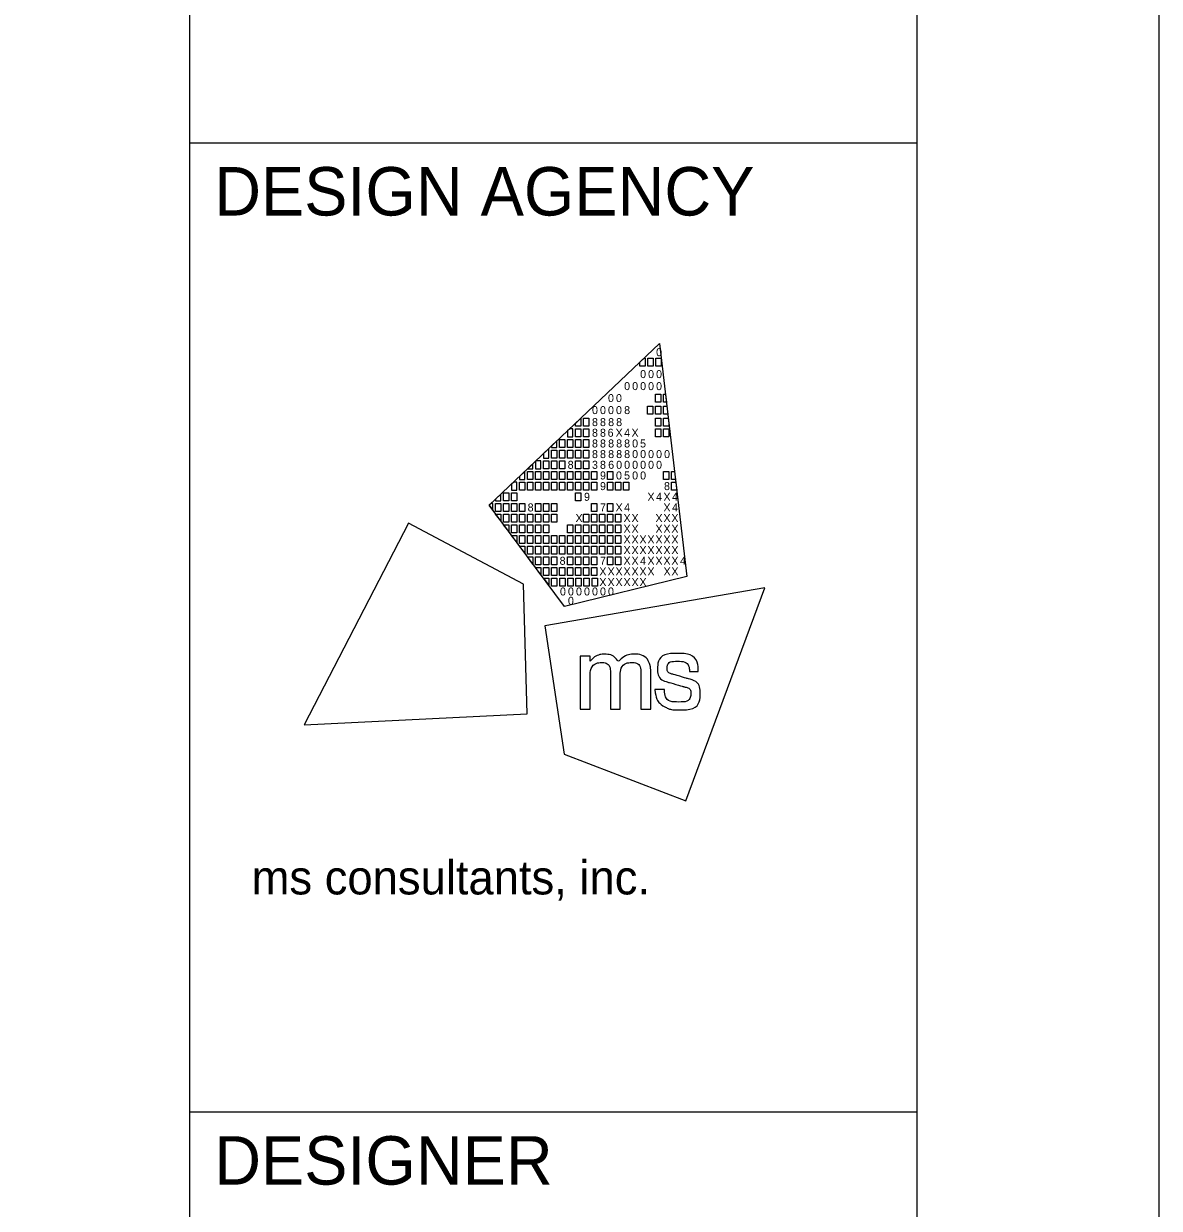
# Model space of a CAD drawing. Extents: x -3.5 to 34, y 0 to 22.
# Drawn here: x 31.657 to 34, y 2.301 to 4.746 of the extents above; entities that cross this region are included whole.
import ezdxf

# ---------------------------------------------------------------- set-up
doc = ezdxf.new("R2010")
doc.units = 0
for name, color, linetype in [('Default', 7, 'Continuous'), ('SH_Border', 7, 'Continuous'), ('SH_Cut_Line', 7, 'Continuous'), ('SH_Data', 7, 'Continuous')]:
    doc.layers.add(name, color=color, linetype=linetype)

msp = doc.modelspace()

# ---------------------------------------------------------------- linework, layer by layer
at = {"layer": 'Default'}
for p, q in [((32.6175, 3.7519), (32.9688, 4.0861)), ((32.9688, 4.0861), (32.9688, 4.0861)), ((32.9688, 4.0861), (33.0253, 3.6052)), ((32.773, 3.543), (32.6175, 3.7519)), ((33.0253, 3.6052), (32.773, 3.543))]:
    msp.add_line(p, q, dxfattribs=at)
for points in [[(32.9279, 4.0472), (32.9369, 4.0558), (32.9389, 4.0558), (32.9389, 4.0393), (32.9279, 4.0393)], [(32.9444, 4.0558), (32.9554, 4.0558), (32.9554, 4.0393), (32.9444, 4.0393)], [(32.9609, 4.0558), (32.9719, 4.0558), (32.9719, 4.0393), (32.9609, 4.0393)], [(32.9606, 3.9815), (32.9716, 3.9815), (32.9716, 3.965), (32.9606, 3.965)], [(32.9771, 3.9815), (32.9811, 3.9815), (32.983, 3.965), (32.9771, 3.965)], [(32.9441, 3.9567), (32.9551, 3.9567), (32.9551, 3.9402), (32.9441, 3.9402)], [(32.9606, 3.9567), (32.9716, 3.9567), (32.9716, 3.9402), (32.9606, 3.9402)], [(32.9771, 3.9567), (32.984, 3.9567), (32.9859, 3.9402), (32.9771, 3.9402)], [(32.7953, 3.9211), (32.8064, 3.9316), (32.8064, 3.9154), (32.7953, 3.9154)], [(32.8123, 3.9319), (32.8233, 3.9319), (32.8233, 3.9154), (32.8123, 3.9154)], [(32.9606, 3.9319), (32.9716, 3.9319), (32.9716, 3.9154), (32.9606, 3.9154)], [(32.9771, 3.9319), (32.9869, 3.9319), (32.9881, 3.9218), (32.9881, 3.9154), (32.9771, 3.9154)], [(32.7627, 3.8879), (32.7737, 3.8879), (32.7737, 3.8714), (32.7627, 3.8714)], [(32.7793, 3.8879), (32.7903, 3.8879), (32.7903, 3.8714), (32.7793, 3.8714)], [(32.7958, 3.9099), (32.8068, 3.9099), (32.8068, 3.8934), (32.7958, 3.8934)], [(32.7958, 3.8879), (32.8068, 3.8879), (32.8068, 3.8714), (32.7958, 3.8714)], [(32.8123, 3.9099), (32.8233, 3.9099), (32.8233, 3.8934), (32.8123, 3.8934)], [(32.8123, 3.8879), (32.8233, 3.8879), (32.8233, 3.8714), (32.8123, 3.8714)], [(32.9606, 3.9099), (32.9716, 3.9099), (32.9716, 3.8934), (32.9606, 3.8934)], [(32.9771, 3.9099), (32.9881, 3.9099), (32.9881, 3.8934), (32.9771, 3.8934)], [(32.7462, 3.8659), (32.7572, 3.8659), (32.7572, 3.8494), (32.7462, 3.8494)], [(32.7627, 3.8659), (32.7737, 3.8659), (32.7737, 3.8494), (32.7627, 3.8494)], [(32.7793, 3.8659), (32.7903, 3.8659), (32.7903, 3.8494), (32.7793, 3.8494)], [(32.7958, 3.8659), (32.8068, 3.8659), (32.8068, 3.8494), (32.7958, 3.8494)], [(32.8123, 3.8659), (32.8233, 3.8659), (32.8233, 3.8494), (32.8123, 3.8494)], [(32.7297, 3.8439), (32.7407, 3.8439), (32.7407, 3.8273), (32.7297, 3.8273)], [(32.7462, 3.8439), (32.7572, 3.8439), (32.7572, 3.8273), (32.7462, 3.8273)], [(32.7627, 3.8439), (32.7737, 3.8439), (32.7737, 3.8273), (32.7627, 3.8273)], [(32.7958, 3.8439), (32.8068, 3.8439), (32.8068, 3.8273), (32.7958, 3.8273)], [(32.8123, 3.8439), (32.8233, 3.8439), (32.8233, 3.8273), (32.8123, 3.8273)], [(32.6967, 3.8218), (32.7077, 3.8218), (32.7077, 3.8053), (32.6967, 3.8053)], [(32.7132, 3.8218), (32.7242, 3.8218), (32.7242, 3.8053), (32.7132, 3.8053)], [(32.7297, 3.8218), (32.7407, 3.8218), (32.7407, 3.8053), (32.7297, 3.8053)], [(32.7462, 3.8218), (32.7572, 3.8218), (32.7572, 3.8053), (32.7462, 3.8053)], [(32.7627, 3.8218), (32.7737, 3.8218), (32.7737, 3.8053), (32.7627, 3.8053)], [(32.7793, 3.8218), (32.7903, 3.8218), (32.7903, 3.8053), (32.7793, 3.8053)], [(32.7958, 3.8218), (32.8068, 3.8218), (32.8068, 3.8053), (32.7958, 3.8053)], [(32.8123, 3.8218), (32.8233, 3.8218), (32.8233, 3.8053), (32.8123, 3.8053)], [(32.8288, 3.8218), (32.8398, 3.8218), (32.8398, 3.8053), (32.8288, 3.8053)], [(32.8618, 3.8218), (32.8728, 3.8218), (32.8728, 3.8053), (32.8618, 3.8053)], [(32.9771, 3.8218), (32.9881, 3.8218), (32.9881, 3.8053), (32.9771, 3.8053)], [(32.9935, 3.8218), (32.9998, 3.8218), (33.0018, 3.8053), (32.9935, 3.8053)], [(32.6802, 3.7998), (32.6912, 3.7998), (32.6912, 3.7833), (32.6802, 3.7833)], [(32.6967, 3.7998), (32.7077, 3.7998), (32.7077, 3.7833), (32.6967, 3.7833)], [(32.7132, 3.7998), (32.7242, 3.7998), (32.7242, 3.7833), (32.7132, 3.7833)], [(32.7297, 3.7998), (32.7407, 3.7998), (32.7407, 3.7833), (32.7297, 3.7833)], [(32.7462, 3.7998), (32.7572, 3.7998), (32.7572, 3.7833), (32.7462, 3.7833)], [(32.7627, 3.7998), (32.7737, 3.7998), (32.7737, 3.7833), (32.7627, 3.7833)], [(32.7793, 3.7998), (32.7903, 3.7998), (32.7903, 3.7833), (32.7793, 3.7833)], [(32.7958, 3.7998), (32.8068, 3.7998), (32.8068, 3.7833), (32.7958, 3.7833)], [(32.8123, 3.7998), (32.8233, 3.7998), (32.8233, 3.7833), (32.8123, 3.7833)], [(32.8288, 3.7998), (32.8398, 3.7998), (32.8398, 3.7833), (32.8288, 3.7833)], [(32.8618, 3.7998), (32.8728, 3.7998), (32.8728, 3.7833), (32.8618, 3.7833)], [(32.8783, 3.7998), (32.8893, 3.7998), (32.8893, 3.7833), (32.8783, 3.7833)], [(32.8947, 3.7998), (32.9057, 3.7998), (32.9057, 3.7833), (32.8947, 3.7833)], [(32.9935, 3.7998), (33.0024, 3.7998), (33.0044, 3.7833), (32.9935, 3.7833)], [(32.6471, 3.7778), (32.6581, 3.7778), (32.6581, 3.7613), (32.6471, 3.7613)], [(32.6637, 3.7778), (32.6747, 3.7778), (32.6747, 3.7613), (32.6637, 3.7613)], [(32.7958, 3.7778), (32.8068, 3.7778), (32.8068, 3.7613), (32.7958, 3.7613)], [(32.6306, 3.7558), (32.6416, 3.7558), (32.6416, 3.7393), (32.6306, 3.7393)], [(32.6471, 3.7558), (32.6581, 3.7558), (32.6581, 3.7393), (32.6471, 3.7393)], [(32.6637, 3.7558), (32.6747, 3.7558), (32.6747, 3.7393), (32.6637, 3.7393)], [(32.6802, 3.7558), (32.6912, 3.7558), (32.6912, 3.7393), (32.6802, 3.7393)], [(32.7132, 3.7558), (32.7242, 3.7558), (32.7242, 3.7393), (32.7132, 3.7393)], [(32.7297, 3.7558), (32.7407, 3.7558), (32.7407, 3.7393), (32.7297, 3.7393)], [(32.7462, 3.7558), (32.7572, 3.7558), (32.7572, 3.7393), (32.7462, 3.7393)], [(32.8288, 3.7558), (32.8398, 3.7558), (32.8398, 3.7393), (32.8288, 3.7393)], [(32.8618, 3.7558), (32.8728, 3.7558), (32.8728, 3.7393), (32.8618, 3.7393)], [(32.6306, 3.7338), (32.6416, 3.7338), (32.6416, 3.72)], [(32.6471, 3.7338), (32.6581, 3.7338), (32.6581, 3.7173), (32.6471, 3.7173)], [(32.6637, 3.7338), (32.6747, 3.7338), (32.6747, 3.7173), (32.6637, 3.7173)], [(32.6802, 3.7338), (32.6912, 3.7338), (32.6912, 3.7173), (32.6802, 3.7173)], [(32.6967, 3.7338), (32.7077, 3.7338), (32.7077, 3.7173), (32.6967, 3.7173)], [(32.7132, 3.7338), (32.7242, 3.7338), (32.7242, 3.7173), (32.7132, 3.7173)], [(32.7297, 3.7338), (32.7407, 3.7338), (32.7407, 3.7173), (32.7297, 3.7173)], [(32.7462, 3.7338), (32.7572, 3.7338), (32.7572, 3.7173), (32.7462, 3.7173)], [(32.8123, 3.7338), (32.8233, 3.7338), (32.8233, 3.7173), (32.8123, 3.7173)], [(32.8288, 3.7338), (32.8398, 3.7338), (32.8398, 3.7173), (32.8288, 3.7173)], [(32.8453, 3.7338), (32.8563, 3.7338), (32.8563, 3.7173), (32.8453, 3.7173)], [(32.8618, 3.7338), (32.8728, 3.7338), (32.8728, 3.7173), (32.8618, 3.7173)], [(32.8783, 3.7338), (32.8893, 3.7338), (32.8893, 3.7173), (32.8783, 3.7173)], [(32.6471, 3.7117), (32.6581, 3.7117), (32.6581, 3.698)], [(32.6637, 3.7117), (32.6747, 3.7117), (32.6747, 3.6952), (32.6637, 3.6952)], [(32.6802, 3.7117), (32.6912, 3.7117), (32.6912, 3.6952), (32.6802, 3.6952)], [(32.6967, 3.7117), (32.7077, 3.7117), (32.7077, 3.6952), (32.6967, 3.6952)], [(32.7132, 3.7117), (32.7242, 3.7117), (32.7242, 3.6952), (32.7132, 3.6952)], [(32.7297, 3.7117), (32.7407, 3.7117), (32.7407, 3.6952), (32.7297, 3.6952)], [(32.7793, 3.7117), (32.7903, 3.7117), (32.7903, 3.6952), (32.7793, 3.6952)], [(32.7958, 3.7117), (32.8068, 3.7117), (32.8068, 3.6952), (32.7958, 3.6952)], [(32.8123, 3.7117), (32.8233, 3.7117), (32.8233, 3.6952), (32.8123, 3.6952)], [(32.8288, 3.7117), (32.8398, 3.7117), (32.8398, 3.6952), (32.8288, 3.6952)], [(32.8453, 3.7117), (32.8563, 3.7117), (32.8563, 3.6952), (32.8453, 3.6952)], [(32.8618, 3.7117), (32.8728, 3.7117), (32.8728, 3.6952), (32.8618, 3.6952)], [(32.8783, 3.7117), (32.8893, 3.7117), (32.8893, 3.6952), (32.8783, 3.6952)], [(32.6637, 3.6897), (32.6747, 3.6897), (32.6747, 3.676)], [(32.6747, 3.6897), (32.6747, 3.6897), (32.6747, 3.6897)], [(32.6802, 3.6897), (32.6912, 3.6897), (32.6912, 3.6732), (32.6802, 3.6732)], [(32.6802, 3.6677), (32.6912, 3.6677), (32.6912, 3.654)], [(32.6967, 3.6897), (32.7077, 3.6897), (32.7077, 3.6732), (32.6967, 3.6732)], [(32.6967, 3.6677), (32.7077, 3.6677), (32.7077, 3.6512), (32.6967, 3.6512)], [(32.7132, 3.6897), (32.7242, 3.6897), (32.7242, 3.6732), (32.7132, 3.6732)], [(32.7132, 3.6677), (32.7242, 3.6677), (32.7242, 3.6512), (32.7132, 3.6512)], [(32.7297, 3.6897), (32.7407, 3.6897), (32.7407, 3.6732), (32.7297, 3.6732)], [(32.7297, 3.6677), (32.7407, 3.6677), (32.7407, 3.6512), (32.7297, 3.6512)], [(32.7462, 3.6897), (32.7572, 3.6897), (32.7572, 3.6732), (32.7462, 3.6732)], [(32.7462, 3.6677), (32.7572, 3.6677), (32.7572, 3.6512), (32.7462, 3.6512)], [(32.7627, 3.6897), (32.7737, 3.6897), (32.7737, 3.6732), (32.7627, 3.6732)], [(32.7627, 3.6677), (32.7737, 3.6677), (32.7737, 3.6512), (32.7627, 3.6512)], [(32.7793, 3.6897), (32.7903, 3.6897), (32.7903, 3.6732), (32.7793, 3.6732)], [(32.7793, 3.6677), (32.7903, 3.6677), (32.7903, 3.6512), (32.7793, 3.6512)], [(32.7958, 3.6897), (32.8068, 3.6897), (32.8068, 3.6732), (32.7958, 3.6732)], [(32.7958, 3.6677), (32.8068, 3.6677), (32.8068, 3.6512), (32.7958, 3.6512)], [(32.8123, 3.6897), (32.8233, 3.6897), (32.8233, 3.6732), (32.8123, 3.6732)], [(32.8123, 3.6677), (32.8233, 3.6677), (32.8233, 3.6512), (32.8123, 3.6512)], [(32.8288, 3.6897), (32.8398, 3.6897), (32.8398, 3.6732), (32.8288, 3.6732)], [(32.8288, 3.6677), (32.8398, 3.6677), (32.8398, 3.6512), (32.8288, 3.6512)], [(32.8453, 3.6897), (32.8563, 3.6897), (32.8563, 3.6732), (32.8453, 3.6732)], [(32.8453, 3.6677), (32.8563, 3.6677), (32.8563, 3.6512), (32.8453, 3.6512)], [(32.8618, 3.6897), (32.8728, 3.6897), (32.8728, 3.6732), (32.8618, 3.6732)], [(32.8618, 3.6677), (32.8728, 3.6677), (32.8728, 3.6512), (32.8618, 3.6512)], [(32.8783, 3.6897), (32.8893, 3.6897), (32.8893, 3.6732), (32.8783, 3.6732)], [(32.8783, 3.6677), (32.8893, 3.6677), (32.8893, 3.6512), (32.8783, 3.6512)], [(32.7077, 3.6305), (32.6965, 3.6457), (32.7077, 3.6457)], [(32.7132, 3.6457), (32.7242, 3.6457), (32.7242, 3.6292), (32.7132, 3.6292)], [(32.7297, 3.6457), (32.7407, 3.6457), (32.7407, 3.6292), (32.7297, 3.6292)], [(32.7462, 3.6457), (32.7572, 3.6457), (32.7572, 3.6292), (32.7462, 3.6292)], [(32.7793, 3.6457), (32.7903, 3.6457), (32.7903, 3.6292), (32.7793, 3.6292)], [(32.7958, 3.6457), (32.8068, 3.6457), (32.8068, 3.6292), (32.7958, 3.6292)], [(32.8123, 3.6457), (32.8233, 3.6457), (32.8233, 3.6292), (32.8123, 3.6292)], [(32.8288, 3.6457), (32.8398, 3.6457), (32.8398, 3.6292), (32.8288, 3.6292)], [(32.8618, 3.6457), (32.8728, 3.6457), (32.8728, 3.6292), (32.8618, 3.6292)], [(32.8783, 3.6457), (32.8893, 3.6457), (32.8893, 3.6292), (32.8783, 3.6292)], [(32.724, 3.6082), (32.7132, 3.6237), (32.7242, 3.6237)], [(32.7297, 3.6237), (32.7407, 3.6237), (32.7407, 3.6072), (32.7297, 3.6072)], [(32.7462, 3.6237), (32.7572, 3.6237), (32.7572, 3.6072), (32.7462, 3.6072)], [(32.7627, 3.6237), (32.7737, 3.6237), (32.7737, 3.6072), (32.7627, 3.6072)], [(32.7793, 3.6237), (32.7903, 3.6237), (32.7903, 3.6072), (32.7793, 3.6072)], [(32.7958, 3.6237), (32.8068, 3.6237), (32.8068, 3.6072), (32.7958, 3.6072)], [(32.8123, 3.6237), (32.8233, 3.6237), (32.8233, 3.6072), (32.8123, 3.6072)], [(32.8288, 3.6237), (32.8398, 3.6237), (32.8398, 3.6072), (32.8288, 3.6072)], [(32.7302, 3.6017), (32.7407, 3.6017), (32.7408, 3.5875)], [(32.7463, 3.6017), (32.7573, 3.6017), (32.7573, 3.5852), (32.7463, 3.5852)], [(32.763, 3.6017), (32.774, 3.6017), (32.774, 3.5852), (32.763, 3.5852)], [(32.7794, 3.6017), (32.7904, 3.6017), (32.7904, 3.5852), (32.7794, 3.5852)], [(32.796, 3.6017), (32.807, 3.6017), (32.807, 3.5852), (32.796, 3.5852)], [(32.8129, 3.6017), (32.8239, 3.6017), (32.8239, 3.5851), (32.8129, 3.5851)], [(32.8296, 3.6017), (32.8406, 3.6017), (32.8406, 3.5851), (32.8296, 3.5851)]]:
    msp.add_lwpolyline(points, close=True, dxfattribs=at)
for points in [[(32.7903, 3.9099), (32.7836, 3.9099), (32.7793, 3.9058), (32.7793, 3.8934), (32.7903, 3.8934), (32.7903, 3.9099)], [(32.7407, 3.8691), (32.7297, 3.8587), (32.7297, 3.8494), (32.7407, 3.8494), (32.7407, 3.8691)], [(32.7572, 3.8849), (32.7462, 3.8744), (32.7462, 3.8714), (32.7572, 3.8714), (32.7572, 3.8849)], [(32.7242, 3.8439), (32.7141, 3.8439), (32.7132, 3.843), (32.7132, 3.8273), (32.7242, 3.8273), (32.7242, 3.8439)], [(32.6912, 3.822), (32.6802, 3.8115), (32.6802, 3.8053), (32.6912, 3.8053), (32.6912, 3.822)], [(32.7077, 3.8377), (32.6968, 3.8273), (32.7077, 3.8273), (32.7077, 3.8377)], [(32.6747, 3.7998), (32.6679, 3.7998), (32.6637, 3.7958), (32.6637, 3.7833), (32.6747, 3.7833), (32.6747, 3.7998)], [(32.6416, 3.7749), (32.6306, 3.7644), (32.6306, 3.7613), (32.6416, 3.7613), (32.6416, 3.7749)], [(32.6251, 3.7558), (32.6216, 3.7558), (32.6175, 3.7519), (32.6251, 3.7417), (32.6251, 3.7558)], [(32.4512, 3.7149), (32.2359, 3.2988), (32.6956, 3.3215), (32.6884, 3.5892), (32.4512, 3.7149)], [(33.0229, 3.1422), (33.1859, 3.5814), (32.7324, 3.5029), (32.7722, 3.2381), (33.0229, 3.1422)]]:
    msp.add_lwpolyline(points, dxfattribs=at)
for points in [[(32.8048, 3.3315), (32.8048, 3.3315), (32.8048, 3.4409), (32.8048, 3.4409), (32.8048, 3.4409), (32.8255, 3.4409), (32.8255, 3.4409), (32.8255, 3.4409), (32.8255, 3.4297), (32.8255, 3.4297), (32.8346, 3.4399), (32.8457, 3.4445), (32.8555, 3.4445), (32.8688, 3.4445), (32.8791, 3.4372), (32.8837, 3.4266), (32.8915, 3.4381), (32.905, 3.4446), (32.9166, 3.4446), (32.9325, 3.4446), (32.9451, 3.435), (32.9494, 3.4213), (32.9494, 3.4212), (32.9494, 3.4212), (32.9494, 3.4212), (32.9501, 3.419), (32.9506, 3.4172), (32.9506, 3.4071), (32.9506, 3.4071), (32.9506, 3.3314), (32.9506, 3.3314), (32.9506, 3.3314), (32.9303, 3.3314), (32.9303, 3.3314), (32.9303, 3.3314), (32.9303, 3.4048), (32.9303, 3.4048), (32.9303, 3.4201), (32.9219, 3.4274), (32.911, 3.4274), (32.8995, 3.4274), (32.8879, 3.4171), (32.8879, 3.4001), (32.8879, 3.4001), (32.8879, 3.3315), (32.8879, 3.3315), (32.8879, 3.3315), (32.8674, 3.3315), (32.8674, 3.3315), (32.8674, 3.3315), (32.8674, 3.4059), (32.8674, 3.4059), (32.8674, 3.4203), (32.8588, 3.4274), (32.8496, 3.4274), (32.8384, 3.4274), (32.8254, 3.417), (32.8254, 3.3962), (32.8254, 3.3962), (32.8254, 3.3315), (32.8254, 3.3315), (32.8254, 3.3315), (32.8048, 3.3315), (32.8048, 3.3315)], [(32.9595, 3.3709), (32.9595, 3.3709), (32.9595, 3.3717), (32.9595, 3.3717), (32.9595, 3.3717), (32.9603, 3.3717), (32.9603, 3.3717), (32.9603, 3.3717), (32.9783, 3.3717), (32.9783, 3.3717), (32.9783, 3.3717), (32.9789, 3.3717), (32.9789, 3.3717), (32.9789, 3.3717), (32.979, 3.371), (32.979, 3.371), (32.9803, 3.3554), (32.9887, 3.346), (33.009, 3.346), (33.0273, 3.346), (33.0333, 3.3554), (33.0333, 3.3631), (33.0333, 3.3732), (33.0256, 3.3758), (33.0175, 3.378), (33.0175, 3.378), (32.987, 3.3867), (32.987, 3.3867), (32.972, 3.3909), (32.9648, 3.4019), (32.9648, 3.4142), (32.9648, 3.4303), (32.9768, 3.4462), (33.0052, 3.4462), (33.0348, 3.4462), (33.0489, 3.4285), (33.0489, 3.4095), (33.0489, 3.4095), (33.0489, 3.4087), (33.0489, 3.4087), (33.0489, 3.4087), (33.0482, 3.4087), (33.0482, 3.4087), (33.0482, 3.4087), (33.0312, 3.4087), (33.0312, 3.4087), (33.0312, 3.4087), (33.0305, 3.4087), (33.0305, 3.4087), (33.0305, 3.4087), (33.0305, 3.4094), (33.0305, 3.4094), (33.0301, 3.4208), (33.0226, 3.43), (33.0056, 3.43), (32.9891, 3.43), (32.9843, 3.4218), (32.9843, 3.4157), (32.9843, 3.4108), (32.9869, 3.4059), (32.9959, 3.4033), (32.9959, 3.4033), (33.0255, 3.3948), (33.0255, 3.3948), (33.0462, 3.3889), (33.0527, 3.3777), (33.0527, 3.3639), (33.0527, 3.3462), (33.041, 3.3298), (33.0087, 3.3298), (32.9952, 3.3298), (32.9877, 3.3321), (32.9823, 3.3348), (32.969, 3.3414), (32.9609, 3.3536), (32.9595, 3.3709)]]:
    msp.add_open_spline(points, degree=3, dxfattribs=at)
at = {"layer": 'SH_Border'}
for p, q in [((32, 0.5), (32, 21.5)), ((32, 4.5), (33.5, 4.5)), ((32, 2.5), (33.5, 2.5))]:
    msp.add_line(p, q, dxfattribs=at)
msp.add_lwpolyline([(1.5, 21.5), (33.5, 21.5), (33.5, 0.5), (1.5, 0.5)], close=True, dxfattribs=at)
at = {"layer": 'SH_Cut_Line'}
msp.add_lwpolyline([(0, 0), (34, 0), (34, 22), (0, 22)], close=True, dxfattribs=at)
at = {"layer": 'SH_Data'}
msp.add_line((32.75, 3.5), (32.75, 3.5), dxfattribs=at)

# ---------------------------------------------------------------- texts
at = {"layer": 'Default'}
for s, p in [('0', (32.9617, 4.0597)), ('0', (32.9288, 4.0145)), ('0', (32.9452, 4.0145)), ('0', (32.9617, 4.0145)), ('0', (32.8958, 3.9897)), ('0', (32.9123, 3.9897)), ('0', (32.9288, 3.9897)), ('0', (32.9452, 3.9897)), ('0', (32.9617, 3.9897)), ('0', (32.8625, 3.965)), ('0', (32.879, 3.965)), ('0', (32.8295, 3.9402)), ('0', (32.846, 3.9402)), ('0', (32.8625, 3.9402)), ('0', (32.879, 3.9402)), ('8', (32.8958, 3.9402)), ('8', (32.8295, 3.9154)), ('8', (32.846, 3.9154)), ('8', (32.8628, 3.9154)), ('8', (32.8793, 3.9154)), ('8', (32.8295, 3.8934)), ('8', (32.8295, 3.8713)), ('8', (32.846, 3.8934)), ('8', (32.846, 3.8713)), ('6', (32.8618, 3.8934)), ('8', (32.8628, 3.8713)), ('X', (32.8781, 3.8934)), ('8', (32.8794, 3.8713)), ('4', (32.8958, 3.8934)), ('8', (32.8958, 3.8713)), ('X', (32.911, 3.8934)), ('0', (32.9123, 3.8713)), ('5', (32.9287, 3.8713)), ('8', (32.8295, 3.8494)), ('8', (32.846, 3.8494)), ('8', (32.8628, 3.8494)), ('8', (32.8794, 3.8494)), ('8', (32.8958, 3.8494)), ('0', (32.9123, 3.8494)), ('0', (32.9288, 3.8494)), ('0', (32.9452, 3.8494)), ('0', (32.9617, 3.8494)), ('0', (32.9782, 3.8494)), ('8', (32.7793, 3.8273)), ('3', (32.8295, 3.8273)), ('8', (32.846, 3.8273)), ('6', (32.8629, 3.8273)), ('0', (32.8793, 3.8273)), ('0', (32.8958, 3.8273)), ('0', (32.9123, 3.8273)), ('0', (32.9288, 3.8273)), ('0', (32.9452, 3.8273)), ('0', (32.9617, 3.8273)), ('9', (32.846, 3.8053)), ('0', (32.879, 3.8053)), ('5', (32.8957, 3.8053)), ('0', (32.9123, 3.8053)), ('0', (32.9288, 3.8053)), ('9', (32.846, 3.7833)), ('8', (32.9781, 3.7833)), ('9', (32.813, 3.7613)), ('X', (32.9439, 3.7613)), ('4', (32.9617, 3.7613)), ('X', (32.9769, 3.7613)), ('4', (32.9946, 3.7613)), ('8', (32.6967, 3.7393)), ('7', (32.846, 3.7393)), ('X', (32.8781, 3.7393)), ('4', (32.8958, 3.7393)), ('X', (32.9769, 3.7393)), ('4', (32.9946, 3.7393)), ('X', (32.7955, 3.7173)), ('X', (32.8945, 3.7173)), ('X', (32.911, 3.7173)), ('X', (32.9604, 3.7173)), ('X', (32.9769, 3.7173)), ('X', (32.9933, 3.7173)), ('X', (32.8945, 3.6952)), ('X', (32.911, 3.6952)), ('X', (32.9604, 3.6952)), ('X', (32.9769, 3.6952)), ('X', (32.9933, 3.6952)), ('X', (32.8945, 3.6732)), ('X', (32.8945, 3.6512)), ('X', (32.911, 3.6732)), ('X', (32.911, 3.6512)), ('X', (32.9274, 3.6732)), ('X', (32.9274, 3.6512)), ('X', (32.9439, 3.6732)), ('X', (32.9439, 3.6512)), ('X', (32.9604, 3.6732)), ('X', (32.9604, 3.6512)), ('X', (32.9769, 3.6732)), ('X', (32.9769, 3.6512)), ('X', (32.9933, 3.6732)), ('X', (32.9933, 3.6512)), ('8', (32.7627, 3.6292)), ('7', (32.846, 3.6292)), ('X', (32.8945, 3.6292)), ('X', (32.911, 3.6292)), ('4', (32.9288, 3.6292)), ('X', (32.9439, 3.6292)), ('X', (32.9604, 3.6292)), ('X', (32.9769, 3.6292)), ('X', (32.9933, 3.6292)), ('4', (33.0111, 3.6292)), ('X', (32.8447, 3.6072)), ('X', (32.8616, 3.6072)), ('X', (32.878, 3.6072)), ('X', (32.8945, 3.6072)), ('X', (32.911, 3.6072)), ('X', (32.9274, 3.6072)), ('X', (32.9439, 3.6072)), ('X', (32.9771, 3.6072)), ('X', (32.9933, 3.6072)), ('X', (32.8447, 3.5851)), ('X', (32.8616, 3.5851)), ('X', (32.878, 3.5851)), ('X', (32.8945, 3.5851)), ('X', (32.911, 3.5851)), ('X', (32.9274, 3.5851)), ('0', (32.7634, 3.5659)), ('0', (32.7799, 3.5659)), ('0', (32.7965, 3.5659)), ('0', (32.813, 3.5659)), ('0', (32.8295, 3.5659)), ('0', (32.846, 3.5659)), ('0', (32.8625, 3.5659)), ('0', (32.7799, 3.5467))]:
    msp.add_text(s, height=0.0165, rotation=360, dxfattribs=at).set_placement(p)
at = {"layer": 'SH_Border'}
msp.add_text('ms consultants, inc.', height=0.07, rotation=360, dxfattribs=at).set_placement((32.1273, 2.9489))
at = {"layer": 'SH_Data'}
for s, p in [('DESIGN AGENCY', (32.05, 4.35)), ('DESIGNER', (32.05, 2.35))]:
    msp.add_text(s, height=0.1, dxfattribs=at).set_placement(p)

doc.saveas('drawing.dxf')
